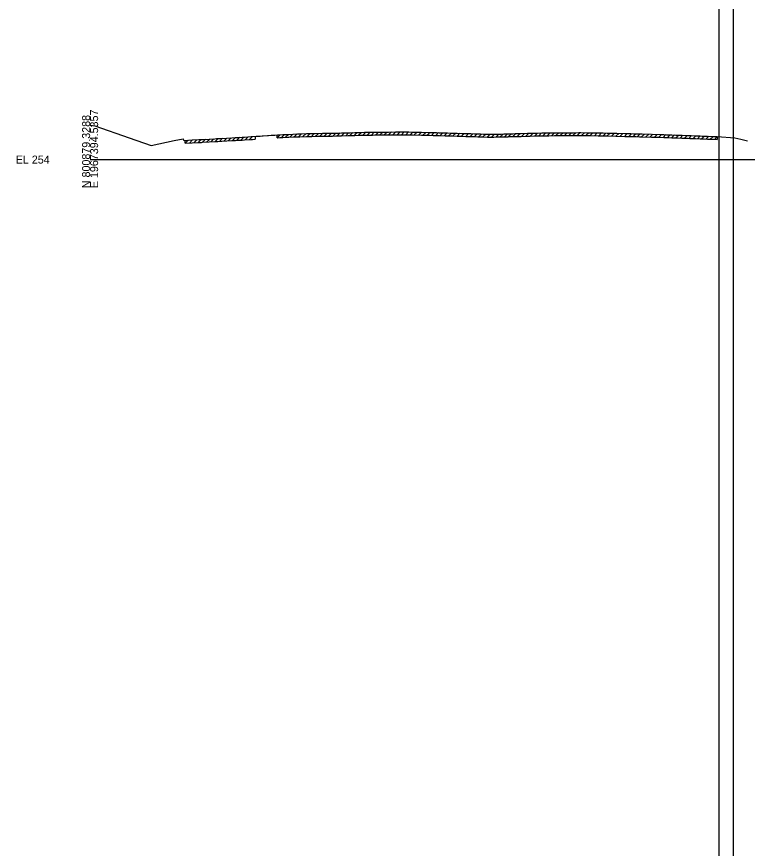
# Model space of a CAD drawing. Extents: x -119 to 6018, y -82 to 34226.
# Drawn here: x -25.7 to 229.9, y 22759.1 to 23050 of the extents above; entities that cross this region are included whole.
import ezdxf

# ---------------------------------------------------------------- set-up
doc = ezdxf.new("R2010")
doc.units = 0
for name, color, linetype in [('Default', 7, 'Continuous'), ('RD_GPK_XS_Cell', 7, 'Continuous'), ('RD_Sketch1', 7, 'Continuous'), ('RD_XS_ExGround', 7, 'Continuous'), ('RD_XS_ExPaveRet', 7, 'Continuous')]:
    doc.layers.add(name, color=color, linetype=linetype)

msp = doc.modelspace()

# ---------------------------------------------------------------- linework, layer by layer
at = {"layer": 'RD_GPK_XS_Cell'}
msp.add_line((0, 23000), (300, 23000), dxfattribs=at)
at = {"layer": 'RD_Sketch1'}
for p, q in [((220, -82), (220, 34226.15)), ((225, -82), (225, 34226.15))]:
    msp.add_line(p, q, dxfattribs=at)
at = {"layer": 'RD_XS_ExGround'}
msp.add_lwpolyline([(0, 23012.01), (1.7, 23011.76), (13.62, 23007.65), (21.36, 23004.93), (29.39, 23006.66), (32.54, 23007.25), (32.65, 23006.8), (33.18, 23006.68), (35.72, 23006.86), (38.07, 23006.98), (38.92, 23007.02), (39.33, 23007.04), (41.6, 23007.17), (43.59, 23007.29), (44.23, 23007.33), (44.69, 23007.35), (46.02, 23007.43), (47.83, 23007.54), (49.59, 23007.64), (50.88, 23007.71), (51.39, 23007.74), (52.07, 23007.78), (53.17, 23007.85), (53.97, 23007.89), (56.29, 23008.03), (56.83, 23008.06), (58.05, 23008.15), (59.53, 23008.23), (60.21, 23008.27), (60.52, 23008.29), (62.01, 23008.39), (62.42, 23008.42), (63.3, 23008.49), (63.87, 23008.54), (64.66, 23008.59), (65.49, 23008.64), (66.34, 23008.69), (67.46, 23008.76), (69.02, 23008.81), (69.45, 23008.83), (71.02, 23008.9), (72.58, 23008.96), (72.89, 23008.97), (73.3, 23008.98), (75.72, 23009.07), (77.55, 23009.13), (78.67, 23009.16), (81.35, 23009.2), (81.81, 23009.21), (83.4, 23009.24), (84.79, 23009.24), (85.94, 23009.26), (87.12, 23009.29), (87.98, 23009.31), (90.24, 23009.38), (90.64, 23009.39), (90.98, 23009.4), (92.56, 23009.45), (94.02, 23009.49), (94.43, 23009.51), (95.98, 23009.56), (97.19, 23009.57), (98.75, 23009.59), (99.63, 23009.6), (100.3, 23009.6), (103.35, 23009.63), (104.36, 23009.64), (106.77, 23009.68), (107.25, 23009.69), (108.75, 23009.71), (109.72, 23009.69), (111.5, 23009.65), (112.76, 23009.62), (115.89, 23009.55), (118.82, 23009.49), (119.98, 23009.47), (121.16, 23009.44), (122.03, 23009.41), (124.24, 23009.34), (124.66, 23009.33), (125.01, 23009.32), (126.56, 23009.27), (128.35, 23009.21), (130.04, 23009.17), (131.36, 23009.13), (132.21, 23009.11), (132.83, 23009.1), (133.2, 23009.08), (134.4, 23009.04), (135.6, 23009), (135.96, 23008.98), (136.59, 23008.95), (137.56, 23008.92), (138.98, 23008.88), (139.4, 23008.87), (141.24, 23008.88), (142.38, 23008.9), (142.96, 23008.91), (143.82, 23008.93), (144.69, 23008.95), (145.75, 23009.01), (146.23, 23009.01), (146.81, 23009.03), (147.87, 23009.06), (148.69, 23009.08), (149.47, 23009.1), (150.02, 23009.11), (150.77, 23009.13), (152.97, 23009.19), (153.92, 23009.21), (156, 23009.26), (158.13, 23009.31), (158.65, 23009.32), (159.04, 23009.33), (160.48, 23009.36), (162.4, 23009.37), (165.26, 23009.39), (166.61, 23009.4), (167.58, 23009.4), (168.33, 23009.41), (169.46, 23009.41), (170.92, 23009.42), (171.58, 23009.42), (173.64, 23009.4), (174.76, 23009.4), (175.15, 23009.39), (177.67, 23009.34), (178.41, 23009.32), (179.44, 23009.3), (180.86, 23009.26), (183.86, 23009.19), (184.24, 23009.19), (186.98, 23009.13), (187.89, 23009.1), (189.08, 23009.07), (190.06, 23009.04), (190.99, 23009.02), (192.11, 23008.99), (193.14, 23008.96), (196.38, 23008.88), (199.33, 23008.8), (200.62, 23008.75), (201.62, 23008.71), (202.39, 23008.68), (203.5, 23008.64), (204.84, 23008.59), (205.52, 23008.56), (206.98, 23008.51), (208.92, 23008.45), (209.77, 23008.42), (210.26, 23008.4), (211.7, 23008.33), (213.35, 23008.26), (214.12, 23008.23), (214.73, 23008.21), (215.95, 23008.16), (217.98, 23008.09), (219.34, 23008.04), (225.54, 23007.63), (227.58, 23007.14), (229.98, 23006.52)], dxfattribs=at)
at = {"layer": 'RD_XS_ExPaveRet'}
for p, q in [((45.26, 23006.38), (46.31, 23007.44)), ((46.76, 23006.47), (47.82, 23007.54)), ((48.26, 23006.56), (49.32, 23007.62)), ((49.76, 23006.65), (50.81, 23007.71)), ((51.26, 23006.73), (52.32, 23007.8)), ((52.76, 23006.82), (53.82, 23007.88)), ((54.26, 23006.91), (55.32, 23007.97)), ((55.76, 23007), (56.82, 23008.06)), ((57.79, 23008.13), (57.79, 23007.13)), ((65.39, 23007.63), (66.45, 23008.69)), ((65.39, 23007.63), (65.39, 23008.63)), ((65.39, 23007.63), (65.49, 23007.64)), ((65.49, 23007.64), (66.34, 23007.69)), ((66.34, 23007.69), (67.46, 23007.76)), ((66.89, 23007.72), (67.95, 23008.78)), ((67.46, 23007.76), (69.02, 23007.81)), ((68.39, 23007.79), (69.43, 23008.83)), ((69.02, 23007.81), (69.45, 23007.83)), ((69.45, 23007.83), (71.02, 23007.9)), ((69.89, 23007.85), (70.94, 23008.89)), ((71.02, 23007.9), (72.58, 23007.96)), ((71.39, 23007.91), (72.43, 23008.95)), ((72.58, 23007.96), (72.89, 23007.97)), ((72.89, 23007.97), (73.93, 23009.01)), ((72.89, 23007.97), (73.3, 23007.98)), ((73.3, 23007.98), (75.72, 23008.07)), ((74.39, 23008.02), (75.43, 23009.06)), ((75.72, 23008.07), (77.55, 23008.13)), ((75.89, 23008.08), (76.93, 23009.11)), ((77.39, 23008.13), (78.42, 23009.16)), ((77.55, 23008.13), (78.67, 23008.16)), ((78.67, 23008.16), (81.35, 23008.2)), ((78.89, 23008.17), (79.91, 23009.18)), ((80.39, 23008.19), (81.41, 23009.2)), ((81.35, 23008.2), (81.81, 23008.21)), ((81.81, 23008.21), (83.4, 23008.24)), ((81.89, 23008.21), (82.91, 23009.23)), ((83.39, 23008.24), (84.39, 23009.24)), ((83.4, 23008.24), (84.79, 23008.24)), ((84.79, 23008.24), (85.94, 23008.26)), ((84.89, 23008.24), (85.91, 23009.26)), ((85.94, 23008.26), (87.12, 23008.29)), ((86.39, 23008.27), (87.42, 23009.3)), ((87.12, 23008.29), (87.98, 23008.31)), ((87.89, 23008.31), (88.92, 23009.34)), ((87.98, 23008.31), (90.24, 23008.38)), ((89.39, 23008.35), (90.42, 23009.38)), ((90.24, 23008.38), (90.64, 23008.39)), ((90.64, 23008.39), (90.98, 23008.4)), ((90.89, 23008.4), (91.92, 23009.43)), ((90.98, 23008.4), (92.56, 23008.45)), ((92.39, 23008.44), (93.43, 23009.47)), ((92.56, 23008.45), (94.02, 23008.49)), ((93.89, 23008.49), (94.93, 23009.53)), ((94.02, 23008.49), (94.43, 23008.51)), ((94.43, 23008.51), (95.98, 23008.56)), ((95.39, 23008.54), (96.42, 23009.57)), ((95.98, 23008.56), (97.19, 23008.57)), ((96.89, 23008.57), (97.9, 23009.58)), ((97.19, 23008.57), (98.75, 23008.59)), ((98.39, 23008.58), (99.4, 23009.59)), ((98.75, 23008.59), (99.63, 23008.6)), ((99.63, 23008.6), (100.3, 23008.6)), ((99.89, 23008.6), (100.9, 23009.61)), ((100.3, 23008.6), (103.35, 23008.63)), ((101.39, 23008.61), (102.4, 23009.62)), ((102.89, 23008.63), (103.91, 23009.64)), ((103.35, 23008.63), (104.36, 23008.64)), ((104.36, 23008.64), (106.77, 23008.68)), ((104.39, 23008.65), (105.41, 23009.66)), ((105.89, 23008.67), (106.91, 23009.68)), ((106.77, 23008.68), (107.25, 23008.69)), ((107.25, 23008.69), (108.75, 23008.71)), ((107.39, 23008.69), (108.41, 23009.7)), ((108.75, 23008.71), (109.72, 23008.69)), ((108.89, 23008.7), (109.88, 23009.69)), ((109.72, 23008.69), (111.5, 23008.65)), ((110.39, 23008.67), (111.37, 23009.65)), ((111.5, 23008.65), (112.76, 23008.62)), ((111.89, 23008.64), (112.87, 23009.61)), ((112.76, 23008.62), (115.89, 23008.55)), ((113.39, 23008.6), (114.37, 23009.58)), ((114.89, 23008.57), (115.87, 23009.55)), ((115.89, 23008.55), (118.82, 23008.49)), ((116.39, 23008.54), (117.37, 23009.52)), ((117.89, 23008.51), (118.87, 23009.49)), ((118.82, 23008.49), (119.98, 23008.47)), ((119.39, 23008.48), (120.37, 23009.46)), ((119.98, 23008.47), (121.16, 23008.44)), ((120.89, 23008.45), (121.86, 23009.42)), ((121.16, 23008.44), (122.03, 23008.41)), ((122.03, 23008.41), (124.24, 23008.34)), ((122.39, 23008.4), (123.36, 23009.37)), ((123.89, 23008.35), (124.86, 23009.32)), ((124.24, 23008.34), (124.66, 23008.33)), ((124.66, 23008.33), (125.01, 23008.32)), ((125.01, 23008.32), (126.56, 23008.27)), ((125.39, 23008.3), (126.36, 23009.27)), ((126.56, 23008.27), (128.35, 23008.21)), ((126.89, 23008.26), (127.86, 23009.23)), ((128.35, 23008.21), (130.04, 23008.17)), ((128.39, 23008.21), (129.37, 23009.19)), ((129.89, 23008.17), (130.87, 23009.15)), ((130.04, 23008.17), (131.36, 23008.13)), ((131.36, 23008.13), (132.21, 23008.11)), ((131.39, 23008.13), (132.37, 23009.11)), ((132.21, 23008.11), (132.83, 23008.1)), ((132.83, 23008.1), (133.2, 23008.08)), ((132.89, 23008.1), (133.85, 23009.06)), ((133.2, 23008.08), (134.4, 23008.04)), ((134.39, 23008.04), (135.36, 23009)), ((134.4, 23008.04), (135.6, 23008)), ((135.6, 23008), (135.96, 23007.98)), ((135.89, 23007.98), (136.86, 23008.94)), ((135.96, 23007.98), (136.59, 23007.95)), ((136.59, 23007.95), (137.56, 23007.92)), ((137.39, 23007.93), (138.36, 23008.9)), ((137.56, 23007.92), (138.98, 23007.88)), ((138.89, 23007.88), (139.88, 23008.87)), ((138.98, 23007.88), (139.4, 23007.87)), ((139.4, 23007.87), (141.24, 23007.88)), ((140.39, 23007.88), (141.4, 23008.89)), ((141.24, 23007.88), (142.38, 23007.9)), ((141.89, 23007.89), (142.91, 23008.91)), ((142.38, 23007.9), (142.96, 23007.91)), ((142.96, 23007.91), (143.82, 23007.93)), ((143.39, 23007.92), (144.42, 23008.94)), ((143.82, 23007.93), (144.69, 23007.95)), ((144.69, 23007.95), (145.75, 23008.01)), ((144.89, 23007.96), (145.94, 23009.01)), ((145.75, 23008.01), (146.23, 23008.01)), ((146.23, 23008.01), (146.81, 23008.03)), ((146.39, 23008.02), (147.42, 23009.04)), ((146.81, 23008.03), (147.87, 23008.06)), ((147.87, 23008.06), (148.69, 23008.08)), ((147.89, 23008.06), (148.92, 23009.08)), ((148.69, 23008.08), (149.47, 23008.1)), ((149.39, 23008.1), (150.42, 23009.12)), ((149.47, 23008.1), (150.02, 23008.11)), ((150.02, 23008.11), (150.77, 23008.13)), ((150.77, 23008.13), (152.97, 23008.19)), ((150.89, 23008.13), (151.92, 23009.16)), ((152.39, 23008.17), (153.42, 23009.2)), ((152.97, 23008.19), (153.92, 23008.21)), ((153.89, 23008.21), (154.92, 23009.23)), ((153.92, 23008.21), (156, 23008.26)), ((155.39, 23008.24), (156.42, 23009.27)), ((156, 23008.26), (158.13, 23008.31)), ((156.89, 23008.28), (157.92, 23009.31)), ((158.13, 23008.31), (158.65, 23008.32)), ((158.39, 23008.32), (159.41, 23009.34)), ((158.65, 23008.32), (159.04, 23008.33)), ((159.04, 23008.33), (160.48, 23008.36)), ((159.89, 23008.35), (160.91, 23009.36)), ((160.48, 23008.36), (162.4, 23008.37)), ((161.39, 23008.36), (162.4, 23009.37)), ((162.4, 23008.37), (165.26, 23008.39)), ((162.89, 23008.37), (163.9, 23009.38)), ((164.39, 23008.38), (165.4, 23009.39)), ((165.26, 23008.39), (166.61, 23008.4)), ((165.89, 23008.39), (166.9, 23009.4)), ((166.61, 23008.4), (167.58, 23008.4)), ((167.39, 23008.4), (168.4, 23009.41)), ((167.58, 23008.4), (168.33, 23008.41)), ((168.33, 23008.41), (169.46, 23008.41)), ((168.89, 23008.41), (169.9, 23009.41)), ((169.46, 23008.41), (170.92, 23008.42)), ((170.39, 23008.41), (171.4, 23009.42)), ((170.92, 23008.42), (171.58, 23008.42)), ((171.58, 23008.42), (173.64, 23008.4)), ((171.89, 23008.42), (172.88, 23009.41)), ((173.39, 23008.4), (174.39, 23009.4)), ((173.64, 23008.4), (174.76, 23008.4)), ((174.76, 23008.4), (175.15, 23008.39)), ((174.89, 23008.39), (175.87, 23009.37)), ((175.15, 23008.39), (177.67, 23008.34)), ((176.39, 23008.36), (177.37, 23009.34)), ((177.67, 23008.34), (178.41, 23008.32)), ((177.89, 23008.33), (178.87, 23009.31)), ((178.41, 23008.32), (179.44, 23008.3)), ((179.39, 23008.3), (180.37, 23009.27)), ((179.44, 23008.3), (180.86, 23008.26)), ((180.86, 23008.26), (183.86, 23008.19)), ((180.89, 23008.26), (181.87, 23009.24)), ((182.39, 23008.23), (183.37, 23009.2)), ((183.86, 23008.19), (184.24, 23008.19)), ((183.89, 23008.19), (184.87, 23009.17)), ((184.24, 23008.19), (186.98, 23008.13)), ((185.39, 23008.16), (186.37, 23009.14)), ((186.89, 23008.13), (187.87, 23009.1)), ((186.98, 23008.13), (187.89, 23008.1)), ((187.89, 23008.1), (189.08, 23008.07)), ((188.39, 23008.09), (189.37, 23009.06)), ((189.08, 23008.07), (190.06, 23008.04)), ((189.89, 23008.05), (190.86, 23009.02)), ((190.06, 23008.04), (190.99, 23008.02)), ((190.99, 23008.02), (192.11, 23007.99)), ((191.39, 23008.01), (192.37, 23008.98)), ((192.11, 23007.99), (193.14, 23007.96)), ((192.89, 23007.97), (193.87, 23008.94)), ((193.14, 23007.96), (196.38, 23007.88)), ((194.39, 23007.93), (195.37, 23008.91)), ((195.89, 23007.9), (196.87, 23008.87)), ((196.38, 23007.88), (199.33, 23007.8)), ((197.39, 23007.85), (198.37, 23008.83)), ((198.89, 23007.81), (199.86, 23008.78)), ((199.33, 23007.8), (200.62, 23007.75)), ((200.39, 23007.76), (201.36, 23008.72)), ((200.62, 23007.75), (201.62, 23007.71)), ((201.62, 23007.71), (202.39, 23007.68)), ((201.89, 23007.7), (202.85, 23008.66)), ((202.39, 23007.68), (203.5, 23007.64)), ((203.39, 23007.64), (204.36, 23008.6)), ((203.5, 23007.64), (204.84, 23007.59)), ((204.84, 23007.59), (205.52, 23007.56)), ((204.89, 23007.58), (205.86, 23008.55)), ((205.52, 23007.56), (206.98, 23007.51)), ((206.39, 23007.53), (207.36, 23008.5)), ((206.98, 23007.51), (208.92, 23007.45)), ((207.89, 23007.48), (208.86, 23008.45)), ((208.92, 23007.45), (209.77, 23007.42)), ((209.39, 23007.43), (210.36, 23008.4)), ((209.77, 23007.42), (210.26, 23007.4)), ((210.89, 23007.37), (211.85, 23008.32)), ((212.39, 23007.3), (213.35, 23008.26)), ((213.89, 23007.24), (214.86, 23008.2)), ((215.39, 23007.18), (216.36, 23008.15)), ((216.89, 23007.13), (217.86, 23008.1)), ((218.39, 23007.08), (219.35, 23008.03)), ((219.35, 23008.03), (219.35, 23007.03)), ((33.26, 23005.69), (34.33, 23006.76)), ((33.26, 23005.69), (33.26, 23006.69)), ((33.26, 23005.69), (35.72, 23005.86)), ((34.76, 23005.79), (35.83, 23006.87)), ((35.72, 23005.86), (38.07, 23005.98)), ((36.26, 23005.89), (37.31, 23006.94)), ((37.76, 23005.96), (38.81, 23007.02)), ((38.07, 23005.98), (38.92, 23006.02)), ((38.92, 23006.02), (39.33, 23006.04)), ((39.26, 23006.04), (40.31, 23007.1)), ((39.33, 23006.04), (41.6, 23006.17)), ((40.76, 23006.12), (41.82, 23007.18)), ((41.6, 23006.17), (43.59, 23006.29)), ((42.26, 23006.21), (43.32, 23007.27)), ((43.59, 23006.29), (44.23, 23006.33)), ((43.76, 23006.3), (44.82, 23007.36)), ((44.23, 23006.33), (44.69, 23006.35)), ((44.69, 23006.35), (46.02, 23006.43)), ((46.02, 23006.43), (47.83, 23006.54)), ((47.83, 23006.54), (49.59, 23006.64)), ((49.59, 23006.64), (50.88, 23006.71)), ((50.88, 23006.71), (51.39, 23006.74)), ((51.39, 23006.74), (52.07, 23006.78)), ((52.07, 23006.78), (53.17, 23006.85)), ((53.17, 23006.85), (53.97, 23006.89)), ((53.97, 23006.89), (56.29, 23007.03)), ((56.29, 23007.03), (56.83, 23007.06)), ((56.83, 23007.06), (57.79, 23007.13)), ((210.26, 23007.4), (211.7, 23007.33)), ((211.7, 23007.33), (213.35, 23007.26)), ((213.35, 23007.26), (214.12, 23007.23)), ((214.12, 23007.23), (214.73, 23007.21)), ((214.73, 23007.21), (215.95, 23007.16)), ((215.95, 23007.16), (217.98, 23007.09)), ((217.98, 23007.09), (219.34, 23007.04)), ((219.34, 23007.04), (219.35, 23007.03))]:
    msp.add_line(p, q, dxfattribs=at)

# ---------------------------------------------------------------- texts
at = {"layer": 'Default'}
msp.add_text('-', height=0.0001, dxfattribs=at).set_placement((0, 23000))
at = {"layer": 'RD_GPK_XS_Cell'}
for s, p in [('E 1967394.5357', (2.8, 22990)), ('N 800879.3288', (0, 22990))]:
    msp.add_text(s, height=2.8, rotation=90, dxfattribs=at).set_placement(p)
msp.add_text('EL 254', height=2.8, dxfattribs=at).set_placement((-26, 22998.6))

doc.saveas('drawing.dxf')
